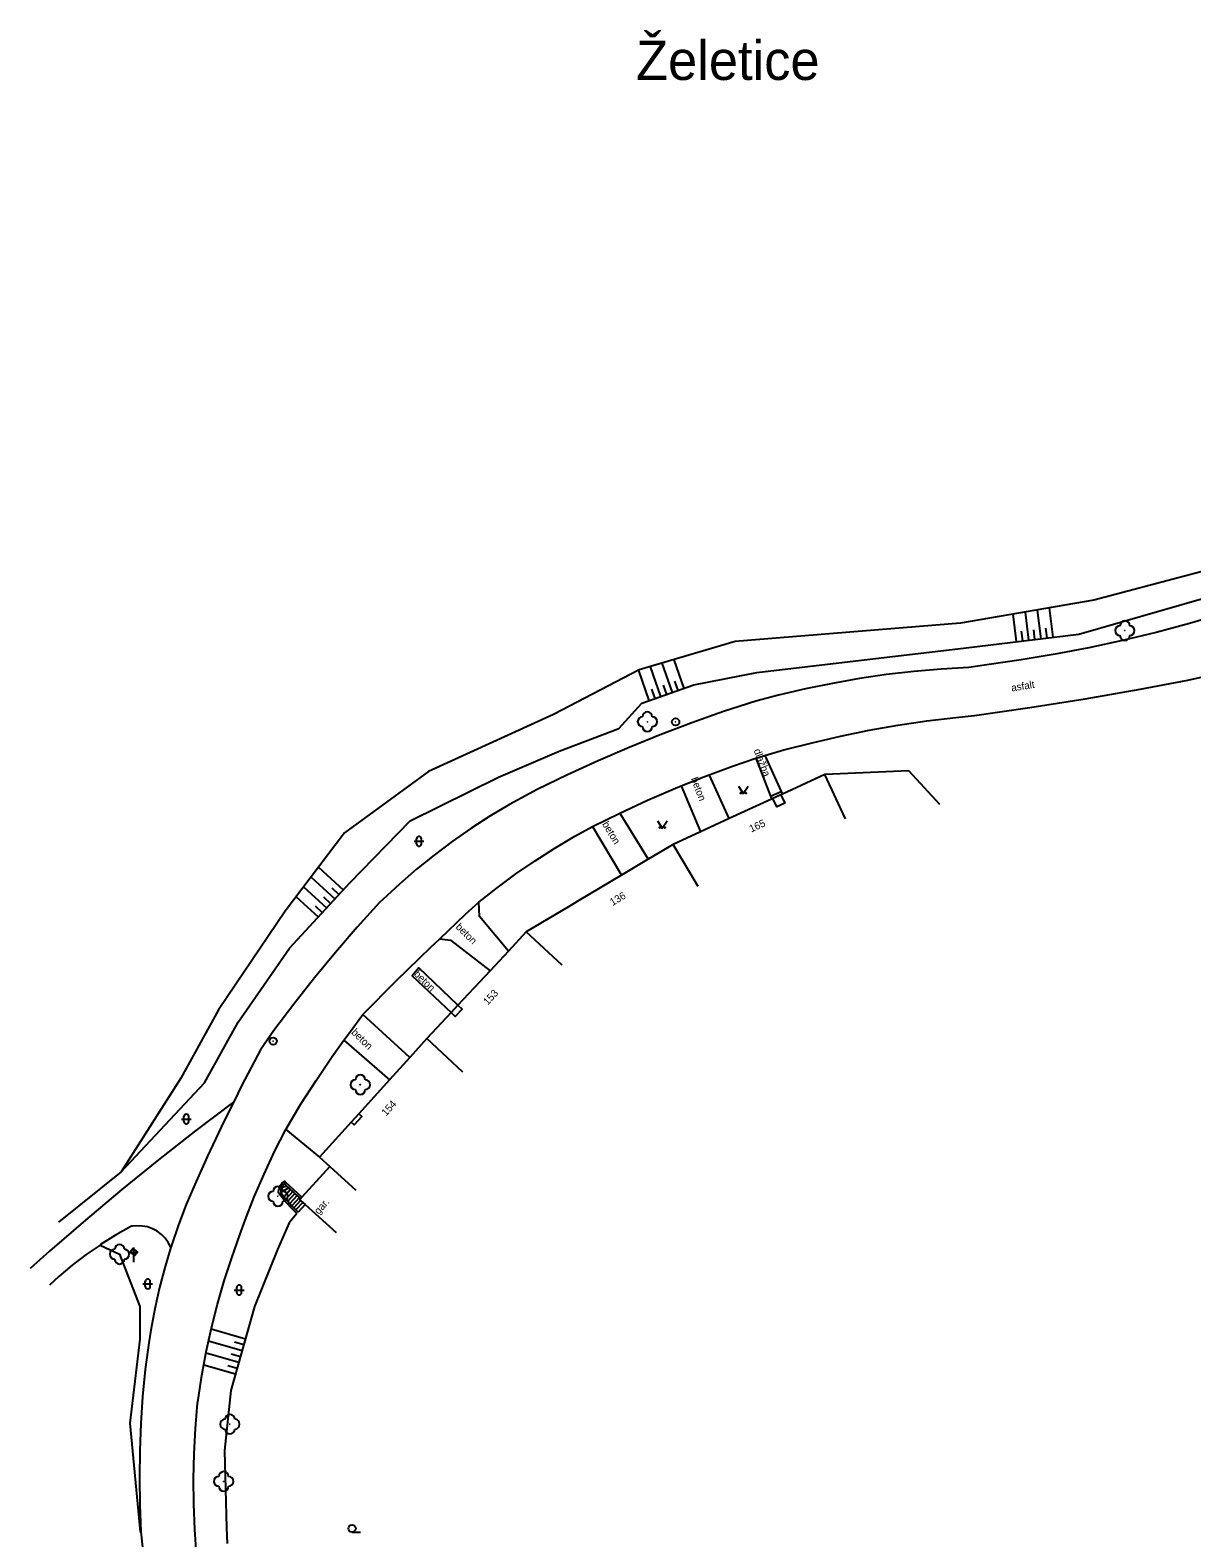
# Model space of a CAD drawing. Extents: x -582162 to -561283, y -1187583 to -1183539.
# Drawn here: x -571434.2 to -571315.7, y -1184217.4 to -1184063.5 of the extents above; entities that cross this region are included whole.
import ezdxf

# ---------------------------------------------------------------- set-up
doc = ezdxf.new("R2010")
doc.units = 0
for name, color, linetype in [('Vrstva 1', 7, 'Continuous'), ('Vrstva 10', 7, 'Continuous'), ('Vrstva 11', 7, 'Continuous'), ('Vrstva 12', 7, 'Continuous'), ('Vrstva 14', 7, 'Continuous'), ('Vrstva 17', 7, 'Continuous'), ('Vrstva 3', 7, 'Continuous'), ('Vrstva 4', 7, 'Continuous'), ('Vrstva 6', 7, 'Continuous'), ('Vrstva 8', 7, 'Continuous'), ('Vrstva 9', 7, 'Continuous')]:
    doc.layers.add(name, color=color, linetype=linetype)

# ---------------------------------------------------------------- blocks, each defined once
blk = doc.blocks.new('1.079')
at = {"layer": 'Vrstva 1'}
for radius in [0.75, 0.001]:
    blk.add_circle((0, -0.001), radius, dxfattribs=at)
blk = doc.blocks.new('3.130')
at = {"layer": 'Vrstva 1'}
blk.add_circle((0, 0), 0.001, dxfattribs=at)
for centre, start, end in [((-1, 0), 90, 270), ((0, 1), 0, 180), ((1, 0), 270, 90), ((0, -1), 180, 360)]:
    blk.add_arc(centre, 1, start, end, dxfattribs=at)
blk = doc.blocks.new('3.040')
at = {"layer": 'Vrstva 1'}
blk.add_line((0, -0.75), (1.75, -0.75), dxfattribs=at)
blk.add_circle((0, 0), 0.75, dxfattribs=at)
blk = doc.blocks.new('3.140')
at = {"layer": 'Vrstva 1'}
blk.add_lwpolyline([(-1, 1.5), (0, 0), (1, 1.5)], dxfattribs=at)
for centre in [(-0.5, 0.1), (0.5, 0.1)]:
    blk.add_circle(centre, 0.1, dxfattribs=at)
blk = doc.blocks.new('3.160')
at = {"layer": 'Vrstva 1'}
for p, q in [((-1, 0), (1, 0)), ((-0.5, -0.5), (-0.5, 0.5)), ((0.5, -0.5), (0.5, 0.5))]:
    blk.add_line(p, q, dxfattribs=at)
for centre, start, end in [((0, 0.5), 0, 180), ((0, -0.5), 180, 360)]:
    blk.add_arc(centre, 0.5, start, end, dxfattribs=at)
blk = doc.blocks.new('4.091')
at = {"layer": 'Vrstva 1'}
for p, q in [((-0.75, 0), (0.75, 0)), ((0, -2), (0, 1))]:
    blk.add_line(p, q, dxfattribs=at)

msp = doc.modelspace()

# ---------------------------------------------------------------- linework, layer by layer
at = {"layer": 'Vrstva 10'}
for points in [[(-571312.56, -1184123.11), (-571315.94, -1184124.09), (-571319.34, -1184124.99), (-571322.76, -1184125.81), (-571326.2, -1184126.56), (-571329.65, -1184127.23), (-571333.12, -1184127.81), (-571336.6, -1184128.32), (-571338.46, -1184128.56), (-571341.26, -1184128.73), (-571344.05, -1184128.98), (-571346.84, -1184129.3), (-571349.62, -1184129.71), (-571352.38, -1184130.2), (-571355.13, -1184130.76), (-571357.86, -1184131.4), (-571360.2, -1184132.02), (-571363.47, -1184133.08), (-571366.72, -1184134.22), (-571369.94, -1184135.44), (-571373.13, -1184136.73), (-571376.29, -1184138.09), (-571379.42, -1184139.53), (-571382.51, -1184141.04), (-571383.32, -1184141.45), (-571385.34, -1184142.57), (-571387.33, -1184143.75), (-571389.27, -1184145.01), (-571391.16, -1184146.33), (-571393.01, -1184147.71), (-571394.81, -1184149.16), (-571396.56, -1184150.67), (-571398.26, -1184152.24), (-571398.59, -1184152.56), (-571400.87, -1184155.07), (-571403.08, -1184157.64), (-571405.24, -1184160.25), (-571407.33, -1184162.92), (-571409.36, -1184165.63), (-571410.75, -1184167.58), (-571412.63, -1184171.19), (-571413.47, -1184172.89)], [(-571359.26, -1184137.55), (-571357.33, -1184136.99), (-571354.45, -1184136.25), (-571351.54, -1184135.58), (-571348.62, -1184134.98), (-571345.68, -1184134.47), (-571342.73, -1184134.03), (-571339.77, -1184133.68), (-571337.86, -1184133.49), (-571332.22, -1184132.67), (-571326.59, -1184131.76), (-571320.98, -1184130.78), (-571316.11, -1184129.86), (-571313.08, -1184129.19)], [(-571367.79, -1184140.65), (-571365.49, -1184139.72), (-571362.56, -1184138.64), (-571360.2, -1184137.82)], [(-571360.2, -1184137.82), (-571359.26, -1184137.55)], [(-571360.2, -1184137.82), (-571358.7, -1184141.72)], [(-571359.26, -1184137.55), (-571357.59, -1184141.22)], [(-571362.92, -1184143.99), (-571364.9, -1184139.57)], [(-571374.07, -1184143.43), (-571371.24, -1184142.12), (-571368.38, -1184140.89), (-571367.79, -1184140.65)], [(-571367.79, -1184140.65), (-571365.82, -1184145.33)], [(-571358.7, -1184141.72), (-571357.59, -1184141.22)], [(-571358.7, -1184141.72), (-571358.59, -1184142)], [(-571357.59, -1184141.22), (-571357.47, -1184141.49)], [(-571376.87, -1184144.81), (-571374.07, -1184143.43)], [(-571374.07, -1184143.43), (-571371.18, -1184148.14)], [(-571388.47, -1184152.53), (-571386.6, -1184151.05), (-571384.68, -1184149.64), (-571382.72, -1184148.29), (-571380.7, -1184147.01), (-571378.65, -1184145.79), (-571376.87, -1184144.81)], [(-571376.87, -1184144.81), (-571373.9, -1184149.76)], [(-571392.44, -1184156.25), (-571389.8, -1184153.76), (-571388.47, -1184152.53)], [(-571385.44, -1184157.52), (-571388.4, -1184153.99), (-571388.47, -1184152.53)], [(-571400.28, -1184163.99), (-571396.84, -1184160.52), (-571393.35, -1184157.11), (-571392.44, -1184156.25)], [(-571392.44, -1184156.25), (-571391.34, -1184156.4), (-571387.3, -1184159.51)], [(-571390.58, -1184163.03), (-571394.56, -1184159.21), (-571395.27, -1184160.04), (-571391.27, -1184163.78)], [(-571402.22, -1184166.6), (-571401.7, -1184165.87), (-571400.28, -1184163.99)], [(-571395.5, -1184168.37), (-571400.28, -1184163.99)], [(-571408.16, -1184175.7), (-571406.65, -1184173.18), (-571405.06, -1184170.7), (-571403.42, -1184168.26), (-571402.22, -1184166.6)], [(-571402.27, -1184166.56), (-571402.22, -1184166.6)], [(-571402.22, -1184166.6), (-571397.58, -1184170.66)], [(-571413.47, -1184172.89), (-571417.34, -1184175.82), (-571421.14, -1184178.8), (-571424.9, -1184181.85), (-571428.6, -1184184.96), (-571432.25, -1184188.13), (-571434.24, -1184189.9)], [(-571413.47, -1184172.89), (-571414.44, -1184174.83), (-571416.18, -1184178.51), (-571417.45, -1184181.32), (-571418.32, -1184183.37), (-571419.11, -1184185.45), (-571419.83, -1184187.55), (-571419.88, -1184187.71)], [(-571417.26, -1184219.11), (-571417.44, -1184216.53), (-571417.54, -1184213.95), (-571417.56, -1184211.37), (-571417.51, -1184208.79), (-571417.37, -1184206.21), (-571417.15, -1184203.64), (-571417.1, -1184203.28), (-571416.72, -1184200.83), (-571416.27, -1184198.39), (-571415.74, -1184195.96), (-571415.12, -1184193.55), (-571414.44, -1184191.16), (-571413.67, -1184188.8), (-571412.83, -1184186.46), (-571412.29, -1184184.96), (-571411.37, -1184182.6), (-571410.37, -1184180.26), (-571409.3, -1184177.96), (-571408.16, -1184175.7)], [(-571408.16, -1184175.7), (-571404.72, -1184178.55)], [(-571406.5, -1184182.63), (-571408.15, -1184181.13)], [(-571407.85, -1184181.66), (-571408.67, -1184182.14)], [(-571408.04, -1184181.49), (-571408.6, -1184181.66)], [(-571407.66, -1184181.84), (-571408.33, -1184182.58)], [(-571408.04, -1184181.49), (-571408.3, -1184181.26)], [(-571407.44, -1184182.04), (-571408.14, -1184182.81)], [(-571407.85, -1184181.66), (-571408.04, -1184181.49)], [(-571407.22, -1184182.24), (-571407.94, -1184183.04)], [(-571407.66, -1184181.84), (-571407.85, -1184181.66)], [(-571406.99, -1184182.44), (-571407.74, -1184183.26)], [(-571407.44, -1184182.04), (-571407.66, -1184181.84)], [(-571406.77, -1184182.64), (-571407.54, -1184183.49)], [(-571407.22, -1184182.24), (-571407.44, -1184182.04)], [(-571406.99, -1184182.44), (-571407.22, -1184182.24)], [(-571406.77, -1184182.64), (-571406.99, -1184182.44)], [(-571406.63, -1184182.77), (-571406.77, -1184182.64)], [(-571406.64, -1184182.95), (-571407.33, -1184183.71)], [(-571406.42, -1184183.15), (-571407.12, -1184183.92)], [(-571419.88, -1184187.71), (-571420.14, -1184187.23), (-571420.46, -1184186.8), (-571420.85, -1184186.42), (-571421.28, -1184186.1), (-571421.76, -1184185.84), (-571422.27, -1184185.66), (-571422.8, -1184185.56), (-571423.35, -1184185.53), (-571423.88, -1184185.59), (-571423.98, -1184185.61), (-571425.54, -1184186.5), (-571427.05, -1184187.46), (-571427.11, -1184187.5)], [(-571427.11, -1184187.5), (-571428.52, -1184188.48), (-571429.94, -1184189.57), (-571431.31, -1184190.72), (-571432.28, -1184191.6)], [(-571427.11, -1184187.5), (-571425.12, -1184188.44), (-571423.06, -1184193.76), (-571423.06, -1184197.09), (-571424.07, -1184205.68), (-571423.03, -1184216.78), (-571422.95, -1184216.77)], [(-571424.03, -1184188.2), (-571423.75, -1184187.86), (-571423.28, -1184188.24), (-571423.55, -1184188.58), (-571424.03, -1184188.2)], [(-571419.88, -1184187.71), (-571420.47, -1184189.68), (-571421.04, -1184191.83), (-571421.53, -1184194), (-571421.94, -1184196.18), (-571422.14, -1184197.47), (-571422.49, -1184200.21), (-571422.76, -1184202.96), (-571422.95, -1184205.72), (-571423.06, -1184208.48), (-571423.09, -1184211.25), (-571423.04, -1184214.01), (-571422.95, -1184216.77)], [(-571422.95, -1184216.77), (-571422.82, -1184218.03), (-571421.42, -1184231.45), (-571418.59, -1184250.04), (-571414.55, -1184269.52), (-571409.56, -1184290.78), (-571402.6, -1184318.09)]]:
    msp.add_lwpolyline(points, dxfattribs=at)
at = {"layer": 'Vrstva 12'}
for points in [[(-571331.48, -1184122.71), (-571331.12, -1184125.64)], [(-571330.25, -1184122.5), (-571329.88, -1184125.48)], [(-571333.95, -1184123.13), (-571333.61, -1184125.94)], [(-571332.71, -1184122.92), (-571332.36, -1184125.78)], [(-571333.11, -1184124.87), (-571332.99, -1184125.86)], [(-571331.86, -1184124.72), (-571331.74, -1184125.71)], [(-571330.62, -1184124.57), (-571330.5, -1184125.56)], [(-571370.97, -1184128.5), (-571369.91, -1184131.53)], [(-571369.77, -1184128.14), (-571368.73, -1184131.12)], [(-571368.57, -1184127.79), (-571367.55, -1184130.71)], [(-571372.17, -1184128.87), (-571371.09, -1184131.95)], [(-571369.65, -1184130.39), (-571369.32, -1184131.33)], [(-571368.47, -1184129.98), (-571368.14, -1184130.91)], [(-571370.83, -1184130.8), (-571370.5, -1184131.74)], [(-571405.58, -1184149.96), (-571403.16, -1184152.19)], [(-571404.82, -1184148.96), (-571402.31, -1184151.27)], [(-571406.34, -1184150.96), (-571404.01, -1184153.11)], [(-571403.47, -1184151.06), (-571402.74, -1184151.73)], [(-571407.1, -1184151.96), (-571404.85, -1184154.03)], [(-571405.16, -1184152.9), (-571404.43, -1184153.57)], [(-571404.31, -1184151.98), (-571403.58, -1184152.65)], [(-571415.76, -1184196.06), (-571412.27, -1184197.06)], [(-571416.04, -1184197.28), (-571412.61, -1184198.26)], [(-571413.39, -1184197.39), (-571412.44, -1184197.66)], [(-571416.29, -1184198.51), (-571412.95, -1184199.46)], [(-571413.74, -1184198.59), (-571412.78, -1184198.86)], [(-571416.53, -1184199.74), (-571413.3, -1184200.66)], [(-571414.08, -1184199.79), (-571413.13, -1184200.06)]]:
    msp.add_lwpolyline(points, dxfattribs=at)
at = {"layer": 'Vrstva 4'}
for points in [[(-571353.14, -1184139.49), (-571357.47, -1184141.49)], [(-571351.05, -1184144.03), (-571353.14, -1184139.49)], [(-571358.59, -1184142), (-571362.92, -1184143.99)], [(-571358.44, -1184141.93), (-571358.59, -1184142)], [(-571357.62, -1184141.56), (-571358.44, -1184141.93)], [(-571357.47, -1184141.49), (-571357.62, -1184141.56)], [(-571365.82, -1184145.33), (-571368.63, -1184146.62)], [(-571368.63, -1184146.62), (-571371.18, -1184148.14)], [(-571366.07, -1184150.92), (-571368.63, -1184146.62)], [(-571373.9, -1184149.76), (-571378.24, -1184152.35)], [(-571379.32, -1184152.99), (-571383.61, -1184155.55)], [(-571383.61, -1184155.55), (-571385.44, -1184157.52)], [(-571379.95, -1184158.95), (-571383.61, -1184155.55)], [(-571387.3, -1184159.51), (-571390.58, -1184163.03)], [(-571391.27, -1184163.78), (-571393.75, -1184166.44)], [(-571390.58, -1184163.03), (-571391.27, -1184163.78)], [(-571393.75, -1184166.44), (-571395.5, -1184168.37)], [(-571390.09, -1184169.85), (-571393.75, -1184166.44)], [(-571397.58, -1184170.66), (-571400.7, -1184174.11)], [(-571401.48, -1184174.98), (-571404.72, -1184178.55)], [(-571400.7, -1184174.11), (-571401.48, -1184174.98)], [(-571403.67, -1184179.5), (-571406.5, -1184182.63)], [(-571404.72, -1184178.55), (-571403.67, -1184179.5)], [(-571403.67, -1184179.5), (-571401.01, -1184181.91)], [(-571406.5, -1184182.63), (-571406.63, -1184182.77)], [(-571406.63, -1184182.77), (-571406.72, -1184182.87), (-571406.64, -1184182.95)], [(-571406.64, -1184182.95), (-571406.42, -1184183.15)], [(-571406.42, -1184183.15), (-571406.18, -1184183.36)], [(-571406.18, -1184183.36), (-571403.02, -1184186.23)]]:
    msp.add_lwpolyline(points, dxfattribs=at)
at = {"layer": 'Vrstva 9'}
for points in [[(-571424.96, -1184180.02), (-571416.44, -1184170.94), (-571413.02, -1184164.76), (-571407.77, -1184157.2), (-571401.63, -1184150.53), (-571395.47, -1184144.21), (-571386.45, -1184139.77), (-571380.27, -1184137.11), (-571374.18, -1184134.8), (-571371.83, -1184132.21), (-571366.5, -1184130.34), (-571360.07, -1184129.08), (-571338.71, -1184126.56), (-571327.21, -1184125.16), (-571310.21, -1184120.29), (-571296.37, -1184114.67), (-571287.46, -1184107), (-571278.62, -1184102.32), (-571264.53, -1184096.88), (-571255.75, -1184091.63), (-571250, -1184086.58)], [(-571265.54, -1184094.21), (-571279.55, -1184100.05), (-571288.88, -1184105.18), (-571297.83, -1184111.55), (-571311.83, -1184118.04), (-571325.69, -1184121.72), (-571339.29, -1184124.05), (-571362.28, -1184125.93), (-571372.09, -1184128.83), (-571380.83, -1184133.37), (-571393.59, -1184139.2), (-571402.15, -1184145.45), (-571408.22, -1184153.43), (-571415.02, -1184163.52), (-571418.88, -1184170.48), (-571424.96, -1184180.02)], [(-571341.4, -1184142.57), (-571344.57, -1184139.13), (-571353.14, -1184139.49)], [(-571357.62, -1184141.56), (-571357.22, -1184142.43), (-571358.04, -1184142.8), (-571358.44, -1184141.93)], [(-571362.92, -1184143.99), (-571365.82, -1184145.33)], [(-571371.18, -1184148.14), (-571373.9, -1184149.76)], [(-571378.24, -1184152.35), (-571379.32, -1184152.99)], [(-571385.44, -1184157.52), (-571387.3, -1184159.51)], [(-571390.58, -1184163.03), (-571390.16, -1184163.42), (-571390.86, -1184164.17), (-571391.27, -1184163.78)], [(-571395.5, -1184168.37), (-571397.58, -1184170.66)], [(-571400.7, -1184174.11), (-571400.4, -1184174.38), (-571401.18, -1184175.24), (-571401.48, -1184174.98)], [(-571424.96, -1184180.02), (-571431.35, -1184185.17)], [(-571407.02, -1184184.3), (-571407.45, -1184183.88), (-571408.2, -1184183.05), (-571408.89, -1184182.18), (-571408.89, -1184182.03), (-571408.84, -1184181.72), (-571408.71, -1184181.42), (-571408.51, -1184181.17), (-571408.26, -1184180.97), (-571408.15, -1184181.13)], [(-571408.15, -1184181.13), (-571408.3, -1184181.26)], [(-571408.6, -1184181.66), (-571408.66, -1184181.83), (-571408.67, -1184182.14)], [(-571408.67, -1184182.14), (-571408.33, -1184182.58)], [(-571408.3, -1184181.26), (-571408.38, -1184181.32), (-571408.56, -1184181.55), (-571408.6, -1184181.66)], [(-571408.33, -1184182.58), (-571408.14, -1184182.81)], [(-571408.14, -1184182.81), (-571408.03, -1184182.95), (-571407.94, -1184183.04)], [(-571407.94, -1184183.04), (-571407.74, -1184183.26)], [(-571407.74, -1184183.26), (-571407.54, -1184183.49)], [(-571407.54, -1184183.49), (-571407.33, -1184183.71)], [(-571407.33, -1184183.71), (-571407.12, -1184183.92)], [(-571407.12, -1184183.92), (-571406.88, -1184184.15)], [(-571406.18, -1184183.36), (-571406.88, -1184184.15)], [(-571407.81, -1184185.24), (-571409, -1184187.97), (-571411.33, -1184193.79), (-571413.77, -1184202.33), (-571414.4, -1184208.46), (-571414.2, -1184216.37)], [(-571407.02, -1184184.3), (-571407.81, -1184185.24)], [(-571414.2, -1184216.37), (-571414.12, -1184217.95)]]:
    msp.add_lwpolyline(points, dxfattribs=at)

# ---------------------------------------------------------------- block references
at = {"layer": 'Vrstva 1', "xscale": 0.5, "yscale": 0.5}
for p in [(-571368.37, -1184134.13), (-571409.45, -1184166.69)]:
    msp.add_blockref('1.079', p, dxfattribs=at)
at = {"layer": 'Vrstva 11', "xscale": 0.5, "yscale": 0.5}
for p in [(-571322.53, -1184124.81), (-571371.25, -1184134.11), (-571400.55, -1184171.14), (-571408.95, -1184182.53), (-571425.12, -1184188.44), (-571413.86, -1184205.78), (-571414.5, -1184211.62)]:
    msp.add_blockref('3.130', p, dxfattribs=at)
at = {"layer": 'Vrstva 3', "xscale": 0.5, "yscale": 0.5}
for name, p in [('3.140', (-571361.47, -1184141.44)), ('3.140', (-571369.73, -1184144.96)), ('3.160', (-571394.56, -1184146.31)), ('3.160', (-571418.3, -1184174.65)), ('3.160', (-571422.24, -1184191.47)), ('3.160', (-571412.91, -1184192.09)), ('3.040', (-571401.39, -1184216.43))]:
    msp.add_blockref(name, p, dxfattribs=at)
at = {"layer": 'Vrstva 8', "xscale": 0.5, "yscale": 0.5}
msp.add_blockref('4.091', (-571423.67, -1184188.26), dxfattribs=at)

# ---------------------------------------------------------------- texts
at = {"layer": 'Vrstva 14'}
for s, rotation, p in [(' asfalt', 9.381, (-571334.34, -1184131.08)), (' dlažba', 291.11, (-571360.52, -1184136.77)), (' beton', 291.11, (-571366.93, -1184139.67)), (' beton', 301.006, (-571376.04, -1184144.31)), (' beton', 315.698, (-571391.08, -1184154.93)), (' beton', 315.698, (-571395.34, -1184159.74)), (' beton', 315.698, (-571401.72, -1184165.68)), (' gar. ', 47.863, (-571404.98, -1184184.63))]:
    msp.add_text(s, height=0.75, rotation=rotation, dxfattribs=at).set_placement(p)
at = {"layer": 'Vrstva 17'}
msp.add_text('Želetice', height=4, dxfattribs=at).set_placement((-571372.41, -1184068.63))
at = {"layer": 'Vrstva 6'}
for s, rotation, p in [('165', 24.712, (-571360.65, -1184145.42)), ('136', 30.785, (-571374.81, -1184152.92)), ('153', 47.069, (-571387.55, -1184163.08)), ('154', 47.827, (-571397.92, -1184174.4))]:
    msp.add_text(s, height=0.75, rotation=rotation, dxfattribs=at).set_placement(p)

doc.saveas('drawing.dxf')
